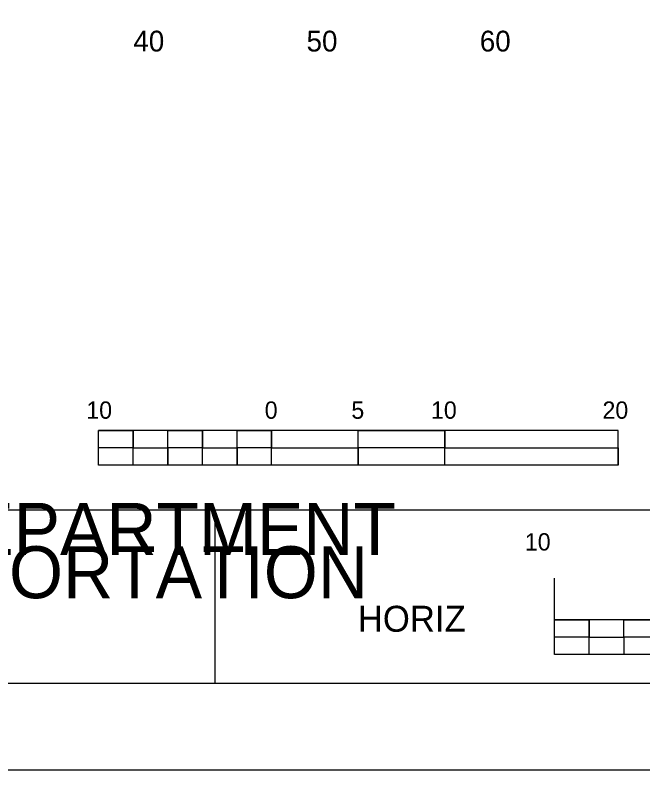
# Model space of a CAD drawing. Extents: x 2193008 to 2198143, y 1236112 to 1237864.
# Drawn here: x 2195420.7 to 2195456.95, y 1237118.04 to 1237161.61 of the extents above; entities that cross this region are included whole.
import ezdxf

# ---------------------------------------------------------------- set-up
doc = ezdxf.new("R2010")
doc.units = 0
for name, color, linetype in [('10', 7, 'Continuous'), ('ANNO-SYMB', 7, 'Continuous'), ('ANNO-TXT', 7, 'Continuous'), ('Level 1', 7, 'Continuous'), ('Level 62', 7, 'Continuous'), ('SHT-BDR', 7, 'Continuous'), ('SHT-BNDRY', 7, 'Continuous')]:
    doc.layers.add(name, color=color, linetype=linetype)

msp = doc.modelspace()

# ---------------------------------------------------------------- linework, layer by layer
at = {"layer": 'ANNO-SYMB'}
for p, q in [((2195451.851, 1237124.7), (2195451.851, 1237129.1)), ((2195471.851, 1237126.7), (2195451.851, 1237126.7)), ((2195453.851, 1237125.7), (2195453.851, 1237126.7)), ((2195453.851, 1237125.7), (2195453.851, 1237126.7)), ((2195471.851, 1237124.7), (2195451.851, 1237124.7))]:
    msp.add_line(p, q, dxfattribs=at)
for points in [[(2195451.851, 1237126.7), (2195453.851, 1237126.7), (2195453.851, 1237125.7), (2195451.851, 1237125.7)], [(2195455.851, 1237126.7), (2195457.851, 1237126.7), (2195457.851, 1237125.7), (2195455.851, 1237125.7)], [(2195453.851, 1237125.7), (2195455.851, 1237125.7), (2195455.851, 1237124.7), (2195453.851, 1237124.7)]]:
    msp.add_lwpolyline(points, close=True, dxfattribs=at)
at = {"layer": 'Level 1'}
for p, q in [((2195455.517, 1237137.63), (2195425.517, 1237137.63)), ((2195425.517, 1237135.63), (2195425.517, 1237137.63)), ((2195427.517, 1237136.63), (2195427.517, 1237137.63)), ((2195431.517, 1237136.63), (2195431.517, 1237137.63)), ((2195435.517, 1237136.63), (2195435.517, 1237137.63)), ((2195435.517, 1237135.63), (2195435.517, 1237137.63)), ((2195440.517, 1237135.63), (2195440.517, 1237137.63)), ((2195445.517, 1237136.63), (2195445.517, 1237137.63)), ((2195445.517, 1237135.63), (2195445.517, 1237137.63)), ((2195455.517, 1237135.63), (2195455.517, 1237137.63)), ((2195427.517, 1237136.63), (2195425.517, 1237136.63)), ((2195429.517, 1237135.63), (2195429.517, 1237136.63)), ((2195431.517, 1237136.63), (2195429.517, 1237136.63)), ((2195433.517, 1237135.63), (2195433.517, 1237136.63)), ((2195435.517, 1237136.63), (2195433.517, 1237136.63)), ((2195440.517, 1237135.63), (2195440.517, 1237136.63)), ((2195445.517, 1237136.63), (2195440.517, 1237136.63)), ((2195455.517, 1237135.63), (2195425.517, 1237135.63)), ((2195429.517, 1237135.63), (2195427.517, 1237135.63)), ((2195433.517, 1237135.63), (2195431.517, 1237135.63)), ((2195440.517, 1237135.63), (2195435.517, 1237135.63)), ((2195455.517, 1237135.63), (2195445.517, 1237135.63))]:
    msp.add_line(p, q, dxfattribs=at)
for points in [[(2195425.517, 1237137.63), (2195427.517, 1237137.63), (2195427.517, 1237136.63), (2195425.517, 1237136.63)], [(2195429.517, 1237137.63), (2195431.517, 1237137.63), (2195431.517, 1237136.63), (2195429.517, 1237136.63)], [(2195433.517, 1237137.63), (2195435.517, 1237137.63), (2195435.517, 1237136.63), (2195433.517, 1237136.63)], [(2195440.517, 1237137.63), (2195445.517, 1237137.63), (2195445.517, 1237136.63), (2195440.517, 1237136.63)], [(2195427.517, 1237136.63), (2195429.517, 1237136.63), (2195429.517, 1237135.63), (2195427.517, 1237135.63)], [(2195431.517, 1237136.63), (2195433.517, 1237136.63), (2195433.517, 1237135.63), (2195431.517, 1237135.63)], [(2195435.517, 1237136.63), (2195440.517, 1237136.63), (2195440.517, 1237135.63), (2195435.517, 1237135.63)], [(2195445.517, 1237136.63), (2195455.517, 1237136.63), (2195455.517, 1237135.63), (2195445.517, 1237135.63)]]:
    msp.add_lwpolyline(points, close=True, dxfattribs=at)
at = {"layer": 'Level 62'}
msp.add_lwpolyline([(2195203.786, 1237118.036), (2195543.786, 1237118.036), (2195543.786, 1237338.036), (2195203.786, 1237338.036)], close=True, dxfattribs=at)
at = {"layer": 'SHT-BDR'}
msp.add_lwpolyline([(2195228.783, 1237133.046), (2195528.783, 1237133.046), (2195528.783, 1237323.046), (2195228.783, 1237323.046)], close=True, dxfattribs=at)
at = {"layer": 'SHT-BNDRY'}
msp.add_line((2195432.256, 1237123.036), (2195432.256, 1237133.046), dxfattribs=at)
msp.add_lwpolyline([(2195216.286, 1237123.036), (2195538.786, 1237123.036), (2195538.786, 1237333.036), (2195216.286, 1237333.036)], close=True, dxfattribs=at)

# ---------------------------------------------------------------- texts
at = {"layer": '10'}
for s, p in [('40', (2195427.532, 1237159.506)), ('50', (2195437.532, 1237159.506)), ('60', (2195447.532, 1237159.506))]:
    msp.add_text(s, height=1.2, dxfattribs=at).set_placement(p)
at = {"layer": 'ANNO-SYMB'}
for s, height, p in [(' 10', 0.9991, (2195449.766, 1237130.7)), ('HORIZ', 1.4994, (2195440.489, 1237126.008))]:
    msp.add_text(s, height=height, rotation=0.0572, dxfattribs=at).set_placement(p)
at = {"layer": 'ANNO-TXT'}
for s, p in [('ALABAMA DEPARTMENT', (2195394.985, 1237130.446)), ('OF TRANSPORTATION', (2195397.396, 1237127.946))]:
    msp.add_text(s, height=3, rotation=360, dxfattribs=at).set_placement(p)
at = {"layer": 'Level 1'}
for s, height, p in [('10', 0.9991, (2195424.817, 1237138.305)), ('0', 1, (2195435.117, 1237138.304)), ('5', 0.999, (2195440.119, 1237138.304)), ('10', 0.9991, (2195444.717, 1237138.305)), ('20', 0.9991, (2195454.618, 1237138.305))]:
    msp.add_text(s, height=height, rotation=0.0572, dxfattribs=at).set_placement(p)

doc.saveas('drawing.dxf')
